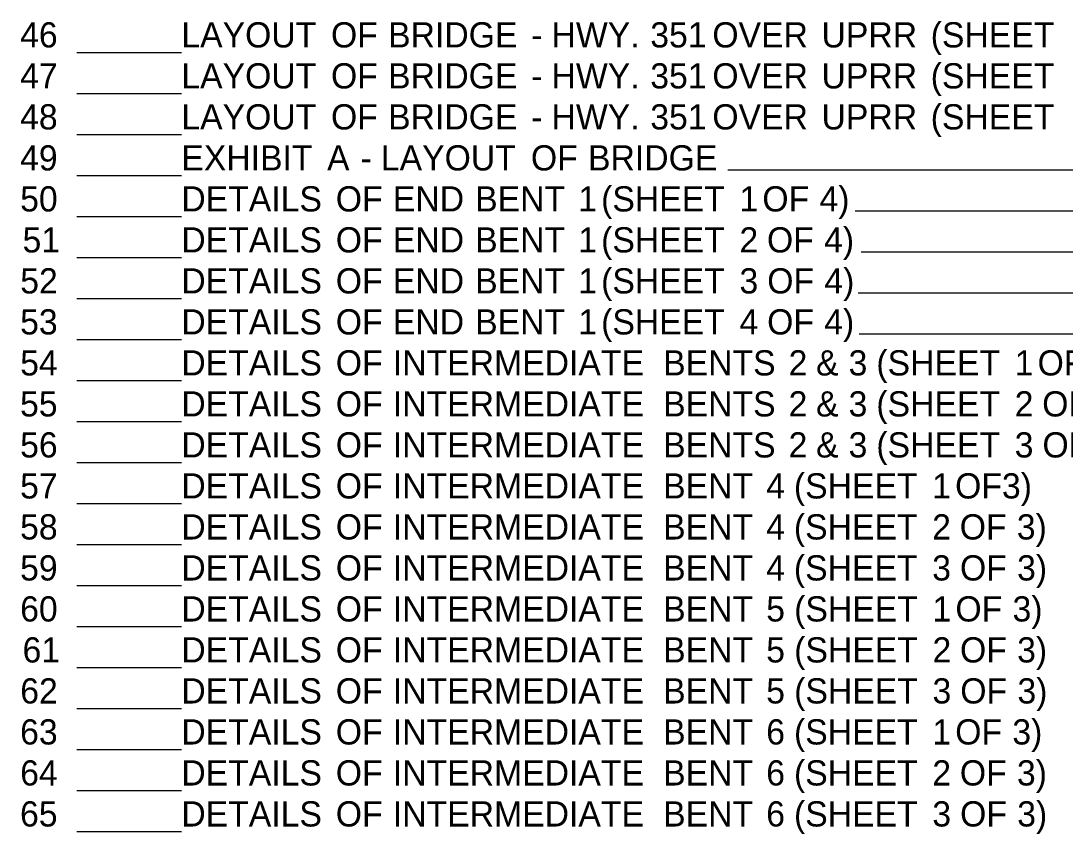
# Model space of a CAD drawing. Extents: x 2 to 32.9, y 0.7 to 21.4.
# Drawn here: x 2.73 to 9.25, y 11.21 to 16.28 of the extents above; entities that cross this region are included whole.
import ezdxf

# ---------------------------------------------------------------- set-up
doc = ezdxf.new("R2010")
doc.units = 0
doc.layers.add('Default', color=7, linetype='Continuous')

msp = doc.modelspace()

# ---------------------------------------------------------------- linework, layer by layer
at = {"layer": 'Default'}
for p, q in [((3.0822, 16.0799), (3.734, 16.0799)), ((3.0822, 16.0799), (3.7084, 16.0799)), ((3.0822, 16.0799), (3.7084, 16.0799)), ((3.0822, 15.8243), (3.734, 15.8243)), ((3.0822, 15.8243), (3.7084, 15.8243)), ((3.0822, 15.8243), (3.7084, 15.8243)), ((3.0822, 15.5687), (3.734, 15.5687)), ((3.0822, 15.5687), (3.7084, 15.5687)), ((3.0822, 15.5687), (3.7084, 15.5687)), ((3.0822, 15.3131), (3.734, 15.3131)), ((3.0822, 15.3131), (3.7084, 15.3131)), ((3.0822, 15.3131), (3.7084, 15.3131)), ((7.1419, 15.3482), (13.6355, 15.3482)), ((3.0822, 15.0575), (3.734, 15.0575)), ((3.0822, 15.0575), (3.7084, 15.0575)), ((3.0822, 15.0575), (3.7084, 15.0575)), ((7.9363, 15.0926), (13.6355, 15.0926)), ((3.0822, 14.8019), (3.734, 14.8019)), ((3.0822, 14.8019), (3.7084, 14.8019)), ((3.0822, 14.8019), (3.7084, 14.8019)), ((7.9731, 14.837), (13.6355, 14.837)), ((3.0822, 14.5463), (3.734, 14.5463)), ((3.0822, 14.5463), (3.7084, 14.5463)), ((3.0822, 14.5463), (3.7084, 14.5463)), ((7.9547, 14.5814), (13.6355, 14.5814)), ((3.0822, 14.2907), (3.734, 14.2907)), ((3.0822, 14.2907), (3.7084, 14.2907)), ((3.0822, 14.2907), (3.7084, 14.2907)), ((7.9609, 14.3258), (13.6355, 14.3258)), ((3.0822, 14.0351), (3.734, 14.0351)), ((3.0822, 14.0351), (3.7084, 14.0351)), ((3.0822, 14.0351), (3.7084, 14.0351)), ((3.0822, 13.7795), (3.734, 13.7795)), ((3.0822, 13.7795), (3.7084, 13.7795)), ((3.0822, 13.7795), (3.7084, 13.7795)), ((3.0822, 13.5239), (3.734, 13.5239)), ((3.0822, 13.5239), (3.7084, 13.5239)), ((3.0822, 13.5239), (3.7084, 13.5239)), ((3.0822, 13.2684), (3.734, 13.2684)), ((3.0822, 13.2684), (3.7084, 13.2684)), ((3.0822, 13.2684), (3.7084, 13.2684)), ((3.0822, 13.0128), (3.734, 13.0128)), ((3.0822, 13.0128), (3.7084, 13.0128)), ((3.0822, 13.0128), (3.7084, 13.0128)), ((3.0822, 12.7572), (3.734, 12.7572)), ((3.0822, 12.7572), (3.7084, 12.7572)), ((3.0822, 12.7572), (3.7084, 12.7572)), ((3.0822, 12.5016), (3.734, 12.5016)), ((3.0822, 12.5016), (3.7084, 12.5016)), ((3.0822, 12.5016), (3.7084, 12.5016)), ((3.0822, 12.246), (3.734, 12.246)), ((3.0822, 12.246), (3.7084, 12.246)), ((3.0822, 12.246), (3.7084, 12.246)), ((3.0822, 11.9904), (3.734, 11.9904)), ((3.0822, 11.9904), (3.7084, 11.9904)), ((3.0822, 11.9904), (3.7084, 11.9904)), ((3.0822, 11.7348), (3.734, 11.7348)), ((3.0822, 11.7348), (3.7084, 11.7348)), ((3.0822, 11.7348), (3.7084, 11.7348)), ((3.0822, 11.4792), (3.734, 11.4792)), ((3.0822, 11.4792), (3.7084, 11.4792)), ((3.0822, 11.4792), (3.7084, 11.4792)), ((3.0822, 11.2236), (3.734, 11.2236)), ((3.0822, 11.2236), (3.7084, 11.2236)), ((3.0822, 11.2236), (3.7084, 11.2236))]:
    msp.add_line(p, q, dxfattribs=at)

# ---------------------------------------------------------------- texts
for s, height, p in [('46', 0.15729, (2.7286, 16.1113)), ('46', 0.15729, (2.7286, 16.1113)), ('LAYOUT', 0.15729, (3.734, 16.1113)), ('LAYOUT', 0.15729, (3.734, 16.1113)), (' OF', 0.15729, (4.6089, 16.1113)), (' OF', 0.15729, (4.6089, 16.1113)), (' BRIDGE', 0.15729, (4.965, 16.1113)), (' BRIDGE', 0.15729, (4.965, 16.1113)), (' HWY.', 0.15729, (5.9843, 16.1113)), (' HWY.', 0.15729, (5.9843, 16.1113)), (' 351', 0.15729, (6.5999, 16.1113)), (' 351', 0.15729, (6.5999, 16.1113)), (' OVER', 0.15729, (6.987, 16.1113)), (' OVER', 0.15729, (6.987, 16.1113)), (' UPRR', 0.15729, (7.6679, 16.1113)), (' UPRR', 0.15729, (7.6679, 16.1113)), (' (SHEET', 0.15729, (8.3487, 16.1113)), (' (SHEET', 0.15729, (8.3487, 16.1113)), (' -', 0.15729, (5.857, 16.1113)), (' -', 0.15729, (5.857, 16.1113)), (' (SHEET', 0.15729, (8.3487, 15.8557)), (' (SHEET', 0.15729, (8.3487, 15.8557)), ('47', 0.15729, (2.7286, 15.8557)), ('47', 0.15729, (2.7286, 15.8557)), ('LAYOUT', 0.15729, (3.734, 15.8557)), ('LAYOUT', 0.15729, (3.734, 15.8557)), (' OF', 0.15729, (4.6089, 15.8557)), (' OF', 0.15729, (4.6089, 15.8557)), (' BRIDGE', 0.15729, (4.965, 15.8557)), (' BRIDGE', 0.15729, (4.965, 15.8557)), (' HWY.', 0.15729, (5.9843, 15.8557)), (' HWY.', 0.15729, (5.9843, 15.8557)), (' 351', 0.15729, (6.5999, 15.8557)), (' 351', 0.15729, (6.5999, 15.8557)), (' OVER', 0.15729, (6.987, 15.8557)), (' OVER', 0.15729, (6.987, 15.8557)), (' UPRR', 0.15729, (7.6679, 15.8557)), (' UPRR', 0.15729, (7.6679, 15.8557)), (' -', 0.15729, (5.857, 15.8557)), (' -', 0.15729, (5.857, 15.8557)), ('48', 0.15729, (2.7285, 15.6001)), ('48', 0.15729, (2.7285, 15.6001)), ('LAYOUT', 0.15729, (3.734, 15.6001)), ('LAYOUT', 0.15729, (3.734, 15.6001)), (' OF', 0.15729, (4.6089, 15.6001)), (' OF', 0.15729, (4.6089, 15.6001)), (' BRIDGE', 0.15729, (4.965, 15.6001)), (' BRIDGE', 0.15729, (4.965, 15.6001)), (' 351', 0.15729, (6.5999, 15.6001)), (' 351', 0.15729, (6.5999, 15.6001)), (' OVER', 0.15729, (6.987, 15.6001)), (' OVER', 0.15729, (6.987, 15.6001)), (' (SHEET', 0.15729, (8.3487, 15.6001)), (' (SHEET', 0.15729, (8.3487, 15.6001)), (' HWY.', 0.15729, (5.9843, 15.6001)), (' HWY.', 0.15729, (5.9843, 15.6001)), (' UPRR', 0.15729, (7.6679, 15.6001)), (' UPRR', 0.15729, (7.6679, 15.6001)), (' -', 0.15729, (5.857, 15.6001)), (' -', 0.15729, (5.857, 15.6001)), ('49', 0.15729, (2.7285, 15.3445)), ('49', 0.15729, (2.7285, 15.3445)), ('EXHIBIT', 0.15729, (3.734, 15.3445)), ('EXHIBIT', 0.15729, (3.734, 15.3445)), (' A', 0.15729, (4.5844, 15.3445)), (' A', 0.15729, (4.5844, 15.3445)), (' LAYOUT', 0.15729, (4.9197, 15.3445)), (' LAYOUT', 0.15729, (4.9197, 15.3445)), (' OF', 0.15729, (5.8557, 15.3445)), (' OF', 0.15729, (5.8557, 15.3445)), (' BRIDGE', 0.15729, (6.2118, 15.3445)), (' BRIDGE', 0.15729, (6.2118, 15.3445)), (' -', 0.15729, (4.7924, 15.3445)), (' -', 0.15729, (4.7924, 15.3445)), ('50', 0.15729, (2.7289, 15.0889)), ('50', 0.15729, (2.7289, 15.0889)), ('DETAILS', 0.15729, (3.734, 15.0889)), ('DETAILS', 0.15729, (3.734, 15.0889)), (' OF', 0.15729, (4.6385, 15.0889)), (' OF', 0.15729, (4.6385, 15.0889)), (' END', 0.15729, (4.9947, 15.0889)), (' END', 0.15729, (4.9947, 15.0889)), (' BENT', 0.15729, (5.508, 15.0889)), (' BENT', 0.15729, (5.508, 15.0889)), (' 1', 0.15729, (6.1508, 15.0889)), (' 1', 0.15729, (6.1508, 15.0889)), (' (SHEET', 0.15729, (6.2936, 15.0889)), (' (SHEET', 0.15729, (6.2936, 15.0889)), (' 1', 0.15729, (7.1561, 15.0889)), (' 1', 0.15729, (7.1561, 15.0889)), (' OF', 0.15729, (7.2989, 15.0889)), (' OF', 0.15729, (7.2989, 15.0889)), (' 4)', 0.15729, (7.6551, 15.0889)), (' 4)', 0.15729, (7.6551, 15.0889)), ('51', 0.15729, (2.7438, 14.8334)), ('51', 0.15729, (2.7438, 14.8334)), ('DETAILS', 0.15729, (3.734, 14.8334)), ('DETAILS', 0.15729, (3.734, 14.8334)), (' OF', 0.15729, (4.6385, 14.8334)), (' OF', 0.15729, (4.6385, 14.8334)), (' END', 0.15729, (4.9947, 14.8334)), (' END', 0.15729, (4.9947, 14.8334)), (' BENT', 0.15729, (5.508, 14.8334)), (' BENT', 0.15729, (5.508, 14.8334)), (' 1', 0.15729, (6.1508, 14.8334)), (' 1', 0.15729, (6.1508, 14.8334)), (' (SHEET', 0.15729, (6.2936, 14.8334)), (' (SHEET', 0.15729, (6.2936, 14.8334)), (' 2', 0.15729, (7.1561, 14.8334)), (' 2', 0.15729, (7.1561, 14.8334)), (' OF', 0.15729, (7.3277, 14.8334)), (' OF', 0.15729, (7.3277, 14.8334)), (' 4)', 0.15729, (7.6839, 14.8334)), (' 4)', 0.15729, (7.6839, 14.8334)), ('52', 0.15729, (2.7294, 14.5778)), ('52', 0.15729, (2.7294, 14.5778)), ('DETAILS', 0.15729, (3.734, 14.5778)), ('DETAILS', 0.15729, (3.734, 14.5778)), (' OF', 0.15729, (4.6385, 14.5778)), (' OF', 0.15729, (4.6385, 14.5778)), (' END', 0.15729, (4.9947, 14.5778)), (' END', 0.15729, (4.9947, 14.5778)), (' BENT', 0.15729, (5.508, 14.5778)), (' BENT', 0.15729, (5.508, 14.5778)), (' 1', 0.15729, (6.1508, 14.5778)), (' 1', 0.15729, (6.1508, 14.5778)), (' (SHEET', 0.15729, (6.2936, 14.5778)), (' (SHEET', 0.15729, (6.2936, 14.5778)), (' 3', 0.15729, (7.1561, 14.5778)), (' 3', 0.15729, (7.1561, 14.5778)), (' OF', 0.15729, (7.3294, 14.5778)), (' OF', 0.15729, (7.3294, 14.5778)), (' 4)', 0.15729, (7.6855, 14.5778)), (' 4)', 0.15729, (7.6855, 14.5778)), ('53', 0.15729, (2.7286, 14.3222)), ('53', 0.15729, (2.7286, 14.3222)), ('DETAILS', 0.15729, (3.734, 14.3222)), ('DETAILS', 0.15729, (3.734, 14.3222)), (' OF', 0.15729, (4.6385, 14.3222)), (' OF', 0.15729, (4.6385, 14.3222)), (' END', 0.15729, (4.9947, 14.3222)), (' END', 0.15729, (4.9947, 14.3222)), (' BENT', 0.15729, (5.508, 14.3222)), (' BENT', 0.15729, (5.508, 14.3222)), (' 1', 0.15729, (6.1508, 14.3222)), (' 1', 0.15729, (6.1508, 14.3222)), (' (SHEET', 0.15729, (6.2936, 14.3222)), (' (SHEET', 0.15729, (6.2936, 14.3222)), (' 4', 0.15729, (7.1561, 14.3222)), (' 4', 0.15729, (7.1561, 14.3222)), (' OF', 0.15729, (7.3287, 14.3222)), (' OF', 0.15729, (7.3287, 14.3222)), (' 4)', 0.15729, (7.6848, 14.3222)), (' 4)', 0.15729, (7.6848, 14.3222)), ('54', 0.15729, (2.729, 14.0666)), ('54', 0.15729, (2.729, 14.0666)), ('DETAILS', 0.15729, (3.734, 14.0666)), ('DETAILS', 0.15729, (3.734, 14.0666)), (' OF', 0.15729, (4.6385, 14.0666)), (' OF', 0.15729, (4.6385, 14.0666)), (' INTERMEDIATE', 0.157286, (4.9947, 14.0666)), (' INTERMEDIATE', 0.157286, (4.9947, 14.0666)), (' BENTS', 0.15729, (6.6802, 14.0666)), (' BENTS', 0.15729, (6.6802, 14.0666)), (' 2', 0.15729, (7.4626, 14.0666)), (' 2', 0.15729, (7.4626, 14.0666)), (' &', 0.15729, (7.6341, 14.0666)), (' &', 0.15729, (7.6341, 14.0666)), (' 3', 0.15729, (7.8367, 14.0666)), (' 3', 0.15729, (7.8367, 14.0666)), (' (SHEET', 0.15729, (8.0099, 14.0666)), (' (SHEET', 0.15729, (8.0099, 14.0666)), (' 1', 0.15729, (8.8725, 14.0666)), (' 1', 0.15729, (8.8725, 14.0666)), (' OF', 0.15729, (9.0153, 14.0666)), (' OF', 0.15729, (9.0153, 14.0666)), ('55', 0.15729, (2.728, 13.811)), ('55', 0.15729, (2.728, 13.811)), ('DETAILS', 0.15729, (3.734, 13.811)), ('DETAILS', 0.15729, (3.734, 13.811)), (' OF', 0.15729, (4.6385, 13.811)), (' OF', 0.15729, (4.6385, 13.811)), (' INTERMEDIATE', 0.157286, (4.9947, 13.811)), (' INTERMEDIATE', 0.157286, (4.9947, 13.811)), (' BENTS', 0.15729, (6.6802, 13.811)), (' BENTS', 0.15729, (6.6802, 13.811)), (' 2', 0.15729, (7.4626, 13.811)), (' 2', 0.15729, (7.4626, 13.811)), (' &', 0.15729, (7.6341, 13.811)), (' &', 0.15729, (7.6341, 13.811)), (' 3', 0.15729, (7.8367, 13.811)), (' 3', 0.15729, (7.8367, 13.811)), (' (SHEET', 0.15729, (8.0099, 13.811)), (' (SHEET', 0.15729, (8.0099, 13.811)), (' 2', 0.15729, (8.8725, 13.811)), (' 2', 0.15729, (8.8725, 13.811)), (' OF', 0.15729, (9.0441, 13.811)), (' OF', 0.15729, (9.0441, 13.811)), ('56', 0.15729, (2.7286, 13.5554)), ('56', 0.15729, (2.7286, 13.5554)), ('DETAILS', 0.15729, (3.734, 13.5554)), ('DETAILS', 0.15729, (3.734, 13.5554)), (' OF', 0.15729, (4.6385, 13.5554)), (' OF', 0.15729, (4.6385, 13.5554)), (' INTERMEDIATE', 0.157286, (4.9947, 13.5554)), (' INTERMEDIATE', 0.157286, (4.9947, 13.5554)), (' BENTS', 0.15729, (6.6802, 13.5554)), (' BENTS', 0.15729, (6.6802, 13.5554)), (' 2', 0.15729, (7.4626, 13.5554)), (' 2', 0.15729, (7.4626, 13.5554)), (' &', 0.15729, (7.6341, 13.5554)), (' &', 0.15729, (7.6341, 13.5554)), (' 3', 0.15729, (7.8367, 13.5554)), (' 3', 0.15729, (7.8367, 13.5554)), (' (SHEET', 0.15729, (8.0099, 13.5554)), (' (SHEET', 0.15729, (8.0099, 13.5554)), (' 3', 0.15729, (8.8725, 13.5554)), (' 3', 0.15729, (8.8725, 13.5554)), (' OF', 0.15729, (9.0457, 13.5554)), (' OF', 0.15729, (9.0457, 13.5554)), ('57', 0.15729, (2.7286, 13.2998)), ('57', 0.15729, (2.7286, 13.2998)), ('DETAILS', 0.15729, (3.734, 13.2998)), ('DETAILS', 0.15729, (3.734, 13.2998)), (' OF', 0.15729, (4.6385, 13.2998)), (' OF', 0.15729, (4.6385, 13.2998)), (' INTERMEDIATE', 0.157286, (4.9947, 13.2998)), (' INTERMEDIATE', 0.157286, (4.9947, 13.2998)), (' BENT', 0.15729, (6.6802, 13.2998)), (' BENT', 0.15729, (6.6802, 13.2998)), (' 4', 0.15729, (7.323, 13.2998)), (' 4', 0.15729, (7.323, 13.2998)), (' (SHEET', 0.15729, (7.4955, 13.2998)), (' (SHEET', 0.15729, (7.4955, 13.2998)), (' 1', 0.15729, (8.3581, 13.2998)), (' 1', 0.15729, (8.3581, 13.2998)), (' OF3)', 0.15729, (8.5009, 13.2998)), (' OF3)', 0.15729, (8.5009, 13.2998)), ('58', 0.15729, (2.7285, 13.0442)), ('58', 0.15729, (2.7285, 13.0442)), ('DETAILS', 0.15729, (3.734, 13.0442)), ('DETAILS', 0.15729, (3.734, 13.0442)), (' OF', 0.15729, (4.6385, 13.0442)), (' OF', 0.15729, (4.6385, 13.0442)), (' INTERMEDIATE', 0.157286, (4.9947, 13.0442)), (' INTERMEDIATE', 0.157286, (4.9947, 13.0442)), (' BENT', 0.15729, (6.6802, 13.0442)), (' BENT', 0.15729, (6.6802, 13.0442)), (' 4', 0.15729, (7.323, 13.0442)), (' 4', 0.15729, (7.323, 13.0442)), (' (SHEET', 0.15729, (7.4955, 13.0442)), (' (SHEET', 0.15729, (7.4955, 13.0442)), (' 2', 0.15729, (8.3581, 13.0442)), (' 2', 0.15729, (8.3581, 13.0442)), (' OF', 0.15729, (8.5296, 13.0442)), (' OF', 0.15729, (8.5296, 13.0442)), (' 3)', 0.15729, (8.8858, 13.0442)), (' 3)', 0.15729, (8.8858, 13.0442)), ('59', 0.15729, (2.7285, 12.7886)), ('59', 0.15729, (2.7285, 12.7886)), ('DETAILS', 0.15729, (3.734, 12.7886)), ('DETAILS', 0.15729, (3.734, 12.7886)), (' OF', 0.15729, (4.6385, 12.7886)), (' OF', 0.15729, (4.6385, 12.7886)), (' INTERMEDIATE', 0.157286, (4.9947, 12.7886)), (' INTERMEDIATE', 0.157286, (4.9947, 12.7886)), (' BENT', 0.15729, (6.6802, 12.7886)), (' BENT', 0.15729, (6.6802, 12.7886)), (' 4', 0.15729, (7.323, 12.7886)), (' 4', 0.15729, (7.323, 12.7886)), (' (SHEET', 0.15729, (7.4955, 12.7886)), (' (SHEET', 0.15729, (7.4955, 12.7886)), (' 3', 0.15729, (8.3581, 12.7886)), (' 3', 0.15729, (8.3581, 12.7886)), (' OF', 0.15729, (8.5313, 12.7886)), (' OF', 0.15729, (8.5313, 12.7886)), (' 3)', 0.15729, (8.8875, 12.7886)), (' 3)', 0.15729, (8.8875, 12.7886)), (' (SHEET', 0.15729, (7.4974, 12.533)), (' (SHEET', 0.15729, (7.4974, 12.533)), (' 3)', 0.15729, (8.859, 12.533)), (' 3)', 0.15729, (8.859, 12.533)), ('60', 0.15729, (2.7289, 12.533)), ('60', 0.15729, (2.7289, 12.533)), ('DETAILS', 0.15729, (3.734, 12.533)), ('DETAILS', 0.15729, (3.734, 12.533)), (' OF', 0.15729, (4.6385, 12.533)), (' OF', 0.15729, (4.6385, 12.533)), (' INTERMEDIATE', 0.157286, (4.9947, 12.533)), (' INTERMEDIATE', 0.157286, (4.9947, 12.533)), (' BENT', 0.15729, (6.6802, 12.533)), (' BENT', 0.15729, (6.6802, 12.533)), (' 5', 0.15729, (7.323, 12.533)), (' 5', 0.15729, (7.323, 12.533)), (' 1', 0.15729, (8.36, 12.533)), (' 1', 0.15729, (8.36, 12.533)), (' OF', 0.15729, (8.5028, 12.533)), (' OF', 0.15729, (8.5028, 12.533)), (' (SHEET', 0.15729, (7.4974, 12.2775)), (' (SHEET', 0.15729, (7.4974, 12.2775)), (' 3)', 0.15729, (8.8877, 12.2775)), (' 3)', 0.15729, (8.8877, 12.2775)), ('61', 0.15729, (2.7438, 12.2775)), ('61', 0.15729, (2.7438, 12.2775)), ('DETAILS', 0.15729, (3.734, 12.2775)), ('DETAILS', 0.15729, (3.734, 12.2775)), (' OF', 0.15729, (4.6385, 12.2775)), (' OF', 0.15729, (4.6385, 12.2775)), (' INTERMEDIATE', 0.157286, (4.9947, 12.2775)), (' INTERMEDIATE', 0.157286, (4.9947, 12.2775)), (' BENT', 0.15729, (6.6802, 12.2775)), (' BENT', 0.15729, (6.6802, 12.2775)), (' 5', 0.15729, (7.323, 12.2775)), (' 5', 0.15729, (7.323, 12.2775)), (' 2', 0.15729, (8.36, 12.2775)), (' 2', 0.15729, (8.36, 12.2775)), (' OF', 0.15729, (8.5316, 12.2775)), (' OF', 0.15729, (8.5316, 12.2775)), ('62', 0.15729, (2.7294, 12.0219)), ('62', 0.15729, (2.7294, 12.0219)), ('DETAILS', 0.15729, (3.734, 12.0219)), ('DETAILS', 0.15729, (3.734, 12.0219)), (' OF', 0.15729, (4.6385, 12.0219)), (' OF', 0.15729, (4.6385, 12.0219)), (' INTERMEDIATE', 0.157286, (4.9947, 12.0219)), (' INTERMEDIATE', 0.157286, (4.9947, 12.0219)), (' BENT', 0.15729, (6.6802, 12.0219)), (' BENT', 0.15729, (6.6802, 12.0219)), (' 5', 0.15729, (7.323, 12.0219)), (' 5', 0.15729, (7.323, 12.0219)), (' (SHEET', 0.15729, (7.4974, 12.0219)), (' (SHEET', 0.15729, (7.4974, 12.0219)), (' 3', 0.15729, (8.36, 12.0219)), (' 3', 0.15729, (8.36, 12.0219)), (' OF', 0.15729, (8.5332, 12.0219)), (' OF', 0.15729, (8.5332, 12.0219)), (' 3)', 0.15729, (8.8894, 12.0219)), (' 3)', 0.15729, (8.8894, 12.0219)), ('63', 0.15729, (2.7286, 11.7663)), ('63', 0.15729, (2.7286, 11.7663)), ('DETAILS', 0.15729, (3.734, 11.7663)), ('DETAILS', 0.15729, (3.734, 11.7663)), (' OF', 0.15729, (4.6385, 11.7663)), (' OF', 0.15729, (4.6385, 11.7663)), (' INTERMEDIATE', 0.157286, (4.9947, 11.7663)), (' INTERMEDIATE', 0.157286, (4.9947, 11.7663)), (' BENT', 0.15729, (6.6802, 11.7663)), (' BENT', 0.15729, (6.6802, 11.7663)), (' 6', 0.15729, (7.323, 11.7663)), (' 6', 0.15729, (7.323, 11.7663)), (' (SHEET', 0.15729, (7.4962, 11.7663)), (' (SHEET', 0.15729, (7.4962, 11.7663)), (' 1', 0.15729, (8.3588, 11.7663)), (' 1', 0.15729, (8.3588, 11.7663)), (' OF', 0.15729, (8.5016, 11.7663)), (' OF', 0.15729, (8.5016, 11.7663)), (' 3)', 0.15729, (8.8578, 11.7663)), (' 3)', 0.15729, (8.8578, 11.7663)), ('64', 0.15729, (2.729, 11.5107)), ('64', 0.15729, (2.729, 11.5107)), ('DETAILS', 0.15729, (3.734, 11.5107)), ('DETAILS', 0.15729, (3.734, 11.5107)), (' OF', 0.15729, (4.6385, 11.5107)), (' OF', 0.15729, (4.6385, 11.5107)), (' INTERMEDIATE', 0.157286, (4.9947, 11.5107)), (' INTERMEDIATE', 0.157286, (4.9947, 11.5107)), (' BENT', 0.15729, (6.6802, 11.5107)), (' BENT', 0.15729, (6.6802, 11.5107)), (' 6', 0.15729, (7.323, 11.5107)), (' 6', 0.15729, (7.323, 11.5107)), (' (SHEET', 0.15729, (7.4962, 11.5107)), (' (SHEET', 0.15729, (7.4962, 11.5107)), (' 2', 0.15729, (8.3588, 11.5107)), (' 2', 0.15729, (8.3588, 11.5107)), (' OF', 0.15729, (8.5304, 11.5107)), (' OF', 0.15729, (8.5304, 11.5107)), (' 3)', 0.15729, (8.8865, 11.5107)), (' 3)', 0.15729, (8.8865, 11.5107)), ('65', 0.15729, (2.728, 11.2551)), ('65', 0.15729, (2.728, 11.2551)), ('DETAILS', 0.15729, (3.734, 11.2551)), ('DETAILS', 0.15729, (3.734, 11.2551)), (' OF', 0.15729, (4.6385, 11.2551)), (' OF', 0.15729, (4.6385, 11.2551)), (' INTERMEDIATE', 0.157286, (4.9947, 11.2551)), (' INTERMEDIATE', 0.157286, (4.9947, 11.2551)), (' BENT', 0.15729, (6.6802, 11.2551)), (' BENT', 0.15729, (6.6802, 11.2551)), (' 6', 0.15729, (7.323, 11.2551)), (' 6', 0.15729, (7.323, 11.2551)), (' (SHEET', 0.15729, (7.4962, 11.2551)), (' (SHEET', 0.15729, (7.4962, 11.2551)), (' 3', 0.15729, (8.3588, 11.2551)), (' 3', 0.15729, (8.3588, 11.2551)), (' OF', 0.15729, (8.532, 11.2551)), (' OF', 0.15729, (8.532, 11.2551)), (' 3)', 0.15729, (8.8882, 11.2551)), (' 3)', 0.15729, (8.8882, 11.2551))]:
    msp.add_text(s, height=height, dxfattribs=at).set_placement(p)

doc.saveas('drawing.dxf')
